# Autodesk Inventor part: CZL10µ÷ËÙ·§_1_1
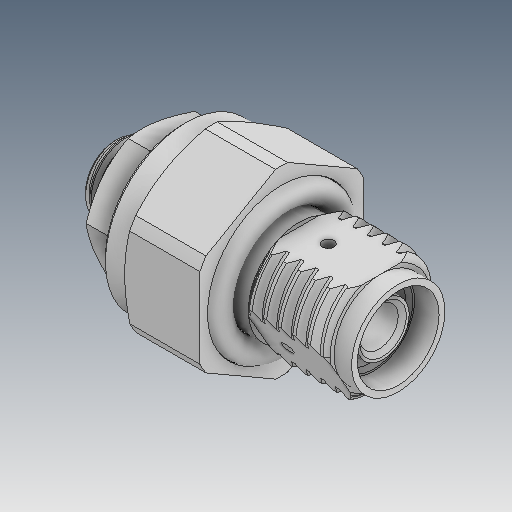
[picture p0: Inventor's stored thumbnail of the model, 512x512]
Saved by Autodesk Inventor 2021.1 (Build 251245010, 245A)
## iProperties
Created: 2019-04
Part Number: CZL10µ÷ËÙ·§_1_1
Material: Ogólny
Document SubType Name: Modeling
Designer: user
Density: 1 g/cm^3
Appearance: Domyślna
Author: user
Revision Number: ÈÎºÎ
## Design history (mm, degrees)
feature "ÊäÈë3"
feature "ÊäÈë4"
feature "ÊäÈë5"
node "Bryła1"
node "Bryła2"
node "Bryła3"
